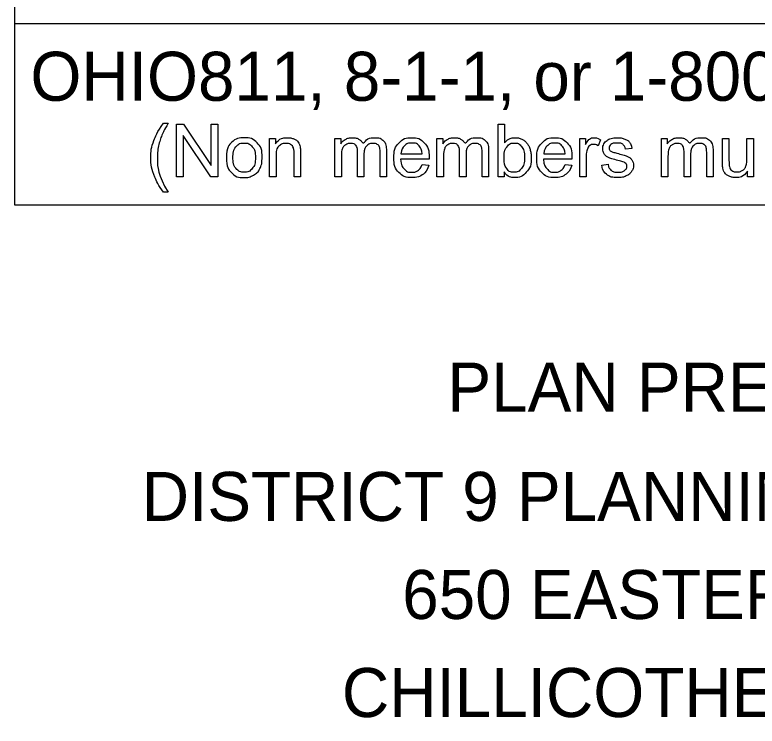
# Model space of a CAD drawing. Extents: x 0 to 82.7, y -0.2 to 22.
# Drawn here: x 53.537 to 55.657, y -0.049 to 1.983 of the extents above; entities that cross this region are included whole.
import ezdxf

# ---------------------------------------------------------------- set-up
doc = ezdxf.new("R2010")
doc.units = 0
doc.layers.add('SH_Data', color=7, linetype='Continuous')
doc.layers.add('SH_Text', color=7, linetype='Continuous')

msp = doc.modelspace()

# ---------------------------------------------------------------- linework, layer by layer
at = {"layer": 'SH_Data'}
for p, q in [((53.5373, 1.4393), (53.5373, 3.7768)), ((57.7873, 1.9571), (53.5373, 1.9571)), ((57.7873, 1.4393), (53.5373, 1.4393))]:
    msp.add_line(p, q, dxfattribs=at)
at = {"layer": 'SH_Text'}
for points in [[(53.9619, 1.6731), (53.9751, 1.6731)], [(53.9986, 1.5204), (53.9986, 1.6705), (54.019, 1.6705), (54.098, 1.5526), (54.098, 1.6705), (54.117, 1.6705), (54.117, 1.5204), (54.0966, 1.5204), (54.0176, 1.6383), (54.0176, 1.5204), (53.9986, 1.5204)], [(54.9341, 1.5204), (54.917, 1.5204), (54.917, 1.6705), (54.9355, 1.6705), (54.9355, 1.617)], [(54.2646, 1.5204), (54.2646, 1.6292), (54.2812, 1.6292), (54.2812, 1.6138)], [(54.451, 1.5204), (54.451, 1.6292), (54.4675, 1.6292), (54.4675, 1.6139)], [(54.7424, 1.5204), (54.7424, 1.6292), (54.7589, 1.6292), (54.7589, 1.6139)], [(55.1502, 1.5204), (55.1502, 1.6292), (55.1668, 1.6292), (55.1668, 1.6127)], [(55.2092, 1.6257), (55.2028, 1.6087)], [(55.3834, 1.5204), (55.3834, 1.6292), (55.3999, 1.6292), (55.3999, 1.6139)], [(55.5577, 1.5618), (55.5577, 1.6292), (55.5761, 1.6292), (55.5761, 1.5689)], [(55.6274, 1.571), (55.6274, 1.6292), (55.6458, 1.6292), (55.6458, 1.5204), (55.6293, 1.5204)], [(54.5341, 1.5836), (54.5341, 1.5204), (54.5157, 1.5204), (54.5157, 1.591)], [(54.5985, 1.5951), (54.5985, 1.5204), (54.5801, 1.5204), (54.5801, 1.5889)], [(54.8255, 1.5836), (54.8255, 1.5204), (54.807, 1.5204), (54.807, 1.591)], [(54.8899, 1.5951), (54.8899, 1.5204), (54.8715, 1.5204), (54.8715, 1.5889)], [(55.2992, 1.6011), (55.2811, 1.5987)], [(55.4665, 1.5836), (55.4665, 1.5204), (55.448, 1.5204), (55.448, 1.591)], [(55.5309, 1.5951), (55.5309, 1.5204), (55.5125, 1.5204), (55.5125, 1.5889)], [(54.283, 1.5798), (54.283, 1.5204), (54.2646, 1.5204)], [(54.3529, 1.5873), (54.3529, 1.5204), (54.3345, 1.5204), (54.3345, 1.5865)], [(54.4694, 1.5768), (54.4694, 1.5204), (54.451, 1.5204)], [(54.7198, 1.5701), (54.6386, 1.5701)], [(54.6396, 1.5852), (54.7004, 1.5852)], [(54.7608, 1.5768), (54.7608, 1.5204), (54.7424, 1.5204)], [(55.1277, 1.5701), (55.0466, 1.5701)], [(55.0476, 1.5852), (55.1084, 1.5852)], [(55.1686, 1.5774), (55.1686, 1.5204), (55.1502, 1.5204)], [(55.4018, 1.5768), (55.4018, 1.5204), (55.3834, 1.5204)], [(54.7002, 1.5555), (54.7192, 1.5531)], [(55.1082, 1.5555), (55.1272, 1.5531)], [(55.2128, 1.5529), (55.231, 1.5558)], [(54.9341, 1.534), (54.9341, 1.5204)], [(55.6293, 1.5204), (55.6293, 1.5365)], [(53.9751, 1.4762), (53.9619, 1.4762)]]:
    msp.add_lwpolyline(points, dxfattribs=at)
for points in [[(53.9619, 1.4762), (53.9466, 1.4955), (53.9361, 1.5213), (53.9255, 1.5471), (53.9255, 1.5747), (53.9255, 1.5991), (53.9334, 1.6214), (53.9426, 1.6474), (53.9619, 1.6731)], [(53.9751, 1.6731), (53.9627, 1.6518), (53.9587, 1.6426), (53.9525, 1.6285), (53.9489, 1.6132), (53.9445, 1.594), (53.9445, 1.5746), (53.9445, 1.5254), (53.9751, 1.4762)], [(54.1411, 1.5748), (54.1411, 1.605), (54.1579, 1.6196), (54.1719, 1.6316), (54.1921, 1.6316), (54.2145, 1.6316), (54.2287, 1.6169), (54.243, 1.6023), (54.243, 1.5764), (54.243, 1.5554), (54.2367, 1.5433), (54.2304, 1.5313), (54.2183, 1.5246), (54.2063, 1.518), (54.1921, 1.518), (54.1693, 1.518), (54.1552, 1.5326), (54.1411, 1.5473), (54.1411, 1.5748)], [(54.1601, 1.5748), (54.1601, 1.5539), (54.1692, 1.5435), (54.1783, 1.5331), (54.1921, 1.5331), (54.2058, 1.5331), (54.2149, 1.5436), (54.224, 1.554), (54.224, 1.5754), (54.224, 1.5956), (54.2148, 1.606), (54.2057, 1.6164), (54.1921, 1.6164), (54.1783, 1.6164), (54.1692, 1.6061), (54.1601, 1.5957), (54.1601, 1.5748)], [(54.2812, 1.6138), (54.2932, 1.6316), (54.3158, 1.6316), (54.3256, 1.6316), (54.3339, 1.6281), (54.3421, 1.6246), (54.3462, 1.6188), (54.3503, 1.6131), (54.3519, 1.6052), (54.3529, 1.6001), (54.3529, 1.5873)], [(54.3345, 1.5865), (54.3345, 1.5978), (54.3324, 1.6034), (54.3302, 1.609), (54.3247, 1.6123), (54.3193, 1.6156), (54.3119, 1.6156), (54.3001, 1.6156), (54.2916, 1.6081), (54.283, 1.6007), (54.283, 1.5798)], [(54.4675, 1.6139), (54.4726, 1.6219), (54.4811, 1.6268), (54.4896, 1.6316), (54.5005, 1.6316), (54.5126, 1.6316), (54.5203, 1.6266), (54.528, 1.6216), (54.5312, 1.6125), (54.5442, 1.6316), (54.5649, 1.6316), (54.5811, 1.6316), (54.5898, 1.6227), (54.5985, 1.6137), (54.5985, 1.5951)], [(54.5157, 1.591), (54.5157, 1.6033), (54.5112, 1.6095), (54.5066, 1.6156), (54.4964, 1.6156), (54.4886, 1.6156), (54.482, 1.6115), (54.4754, 1.6074), (54.4724, 1.5995), (54.4694, 1.5917), (54.4694, 1.5768)], [(54.5801, 1.5889), (54.5801, 1.5999), (54.5783, 1.6048), (54.5765, 1.6097), (54.5718, 1.6126), (54.5671, 1.6156), (54.5607, 1.6156), (54.5493, 1.6156), (54.5417, 1.608), (54.5341, 1.6004), (54.5341, 1.5836)], [(54.7192, 1.5531), (54.7147, 1.5364), (54.7025, 1.5272), (54.6904, 1.518), (54.6714, 1.518), (54.6476, 1.518), (54.6336, 1.5327), (54.6196, 1.5474), (54.6196, 1.5739), (54.6196, 1.6013), (54.6337, 1.6165), (54.6479, 1.6316), (54.6704, 1.6316), (54.6922, 1.6316), (54.706, 1.6168), (54.7199, 1.6019), (54.7199, 1.575), (54.7199, 1.5733), (54.7198, 1.5701)], [(54.7004, 1.5852), (54.6992, 1.5989), (54.6934, 1.6058), (54.6846, 1.6165), (54.6706, 1.6165), (54.6579, 1.6165), (54.6492, 1.608), (54.6406, 1.5995), (54.6396, 1.5852)], [(54.7589, 1.6139), (54.764, 1.6219), (54.7725, 1.6268), (54.781, 1.6316), (54.7919, 1.6316), (54.8039, 1.6316), (54.8117, 1.6266), (54.8194, 1.6216), (54.8226, 1.6125), (54.8355, 1.6316), (54.8562, 1.6316), (54.8725, 1.6316), (54.8812, 1.6227), (54.8899, 1.6137), (54.8899, 1.5951)], [(54.807, 1.591), (54.807, 1.6033), (54.8025, 1.6095), (54.798, 1.6156), (54.7878, 1.6156), (54.78, 1.6156), (54.7734, 1.6115), (54.7667, 1.6074), (54.7638, 1.5995), (54.7608, 1.5917), (54.7608, 1.5768)], [(54.8715, 1.5889), (54.8715, 1.5999), (54.8697, 1.6048), (54.8679, 1.6097), (54.8632, 1.6126), (54.8585, 1.6156), (54.8521, 1.6156), (54.8406, 1.6156), (54.833, 1.608), (54.8255, 1.6004), (54.8255, 1.5836)], [(54.9339, 1.5756), (54.9339, 1.5561), (54.9392, 1.5473), (54.9479, 1.5331), (54.9627, 1.5331), (54.9748, 1.5331), (54.9836, 1.5436), (54.9923, 1.5541), (54.9923, 1.5749), (54.9923, 1.5962), (54.9839, 1.6064), (54.9755, 1.6165), (54.9635, 1.6165), (54.9514, 1.6165), (54.9427, 1.606), (54.9339, 1.5955), (54.9339, 1.5756)], [(54.9355, 1.617), (54.9471, 1.6316), (54.9653, 1.6316), (54.9753, 1.6316), (54.9843, 1.6276), (54.9932, 1.6235), (54.999, 1.6162), (55.0048, 1.6089), (55.0081, 1.5986), (55.0113, 1.5882), (55.0113, 1.5765), (55.0113, 1.5485), (54.9975, 1.5332), (54.9837, 1.518), (54.9643, 1.518), (54.9451, 1.518), (54.9341, 1.534)], [(55.1272, 1.5531), (55.1227, 1.5364), (55.1105, 1.5272), (55.0984, 1.518), (55.0794, 1.518), (55.0555, 1.518), (55.0416, 1.5327), (55.0276, 1.5474), (55.0276, 1.5739), (55.0276, 1.6013), (55.0417, 1.6165), (55.0559, 1.6316), (55.0784, 1.6316), (55.1002, 1.6316), (55.114, 1.6168), (55.1278, 1.6019), (55.1278, 1.575), (55.1278, 1.5733), (55.1277, 1.5701)], [(55.1084, 1.5852), (55.1072, 1.5989), (55.1014, 1.6058), (55.0926, 1.6165), (55.0786, 1.6165), (55.0659, 1.6165), (55.0572, 1.608), (55.0485, 1.5995), (55.0476, 1.5852)], [(55.1668, 1.6127), (55.1731, 1.6243), (55.1785, 1.628), (55.1838, 1.6316), (55.1903, 1.6316), (55.1996, 1.6316), (55.2092, 1.6257)], [(55.2028, 1.6087), (55.196, 1.6126), (55.1893, 1.6126), (55.1833, 1.6126), (55.1785, 1.609), (55.1737, 1.6054), (55.1717, 1.5989), (55.1686, 1.5891), (55.1686, 1.5774)], [(55.2811, 1.5987), (55.2799, 1.6071), (55.274, 1.6118), (55.2681, 1.6165), (55.2573, 1.6165), (55.2446, 1.6165), (55.2391, 1.6123), (55.2337, 1.6081), (55.2337, 1.6025), (55.2337, 1.5989), (55.236, 1.596), (55.2382, 1.593), (55.243, 1.5911), (55.2458, 1.5901), (55.2593, 1.5864), (55.2789, 1.5811), (55.2867, 1.5778), (55.2944, 1.5745), (55.2989, 1.5681), (55.3033, 1.5618), (55.3033, 1.5524), (55.3033, 1.5432), (55.2979, 1.535), (55.2925, 1.5269), (55.2823, 1.5224), (55.2722, 1.518), (55.2594, 1.518), (55.2381, 1.518), (55.227, 1.5268), (55.2158, 1.5356), (55.2128, 1.5529)], [(55.231, 1.5558), (55.2325, 1.5448), (55.2395, 1.5389), (55.2466, 1.5331), (55.2592, 1.5331), (55.272, 1.5331), (55.2781, 1.5383), (55.2843, 1.5435), (55.2843, 1.5504), (55.2843, 1.5567), (55.2788, 1.5603), (55.275, 1.5627), (55.26, 1.5665), (55.2397, 1.5717), (55.2318, 1.5754), (55.224, 1.5791), (55.2199, 1.5857), (55.2159, 1.5923), (55.2159, 1.6003), (55.2159, 1.6076), (55.2192, 1.6138), (55.2225, 1.62), (55.2283, 1.6241), (55.2326, 1.6272), (55.24, 1.6294), (55.2475, 1.6316), (55.256, 1.6316), (55.2688, 1.6316), (55.2785, 1.6279), (55.2882, 1.6243), (55.2928, 1.6179), (55.2974, 1.6116), (55.2992, 1.6011)], [(55.3999, 1.6139), (55.405, 1.6219), (55.4135, 1.6268), (55.422, 1.6316), (55.4329, 1.6316), (55.4449, 1.6316), (55.4527, 1.6266), (55.4604, 1.6216), (55.4636, 1.6125), (55.4765, 1.6316), (55.4972, 1.6316), (55.5135, 1.6316), (55.5222, 1.6227), (55.5309, 1.6137), (55.5309, 1.5951)], [(55.448, 1.591), (55.448, 1.6033), (55.4435, 1.6095), (55.439, 1.6156), (55.4288, 1.6156), (55.421, 1.6156), (55.4144, 1.6115), (55.4077, 1.6074), (55.4048, 1.5995), (55.4018, 1.5917), (55.4018, 1.5768)], [(55.5125, 1.5889), (55.5125, 1.5999), (55.5107, 1.6048), (55.5089, 1.6097), (55.5042, 1.6126), (55.4995, 1.6156), (55.4931, 1.6156), (55.4816, 1.6156), (55.474, 1.608), (55.4665, 1.6004), (55.4665, 1.5836)], [(54.6386, 1.5701), (54.6396, 1.5521), (54.6487, 1.5426), (54.6579, 1.5331), (54.6715, 1.5331), (54.6816, 1.5331), (54.6888, 1.5384), (54.696, 1.5438), (54.7002, 1.5555)], [(55.0466, 1.5701), (55.0476, 1.5521), (55.0567, 1.5426), (55.0659, 1.5331), (55.0795, 1.5331), (55.0896, 1.5331), (55.0968, 1.5384), (55.104, 1.5438), (55.1082, 1.5555)], [(55.5761, 1.5689), (55.5761, 1.5545), (55.5772, 1.5495), (55.579, 1.5422), (55.5846, 1.538), (55.5902, 1.5339), (55.5985, 1.5339), (55.6068, 1.5339), (55.6141, 1.5382), (55.6214, 1.5424), (55.6244, 1.5497), (55.6274, 1.557), (55.6274, 1.571)], [(55.6293, 1.5365), (55.6166, 1.518), (55.5948, 1.518), (55.5852, 1.518), (55.5769, 1.5217), (55.5685, 1.5254), (55.5645, 1.5309), (55.5605, 1.5365), (55.5588, 1.5446), (55.5577, 1.5501), (55.5577, 1.5618)]]:
    msp.add_open_spline(points, degree=3, dxfattribs=at)

# ---------------------------------------------------------------- texts
for s, p in [('OHIO811, 8-1-1, or 1-800-362-2764', (53.5817, 1.7371)), ('PLAN PREPARED BY:', (54.7723, 0.8495)), ('DISTRICT 9 PLANNING & ENGINEERING', (53.8994, 0.5375)), ('650 EASTERN AVENUE', (54.6433, 0.2575)), ('CHILLICOTHE, OHIO 45601', (54.4709, -0.0225))]:
    msp.add_text(s, height=0.14, dxfattribs=at).set_placement(p)

doc.saveas('drawing.dxf')
